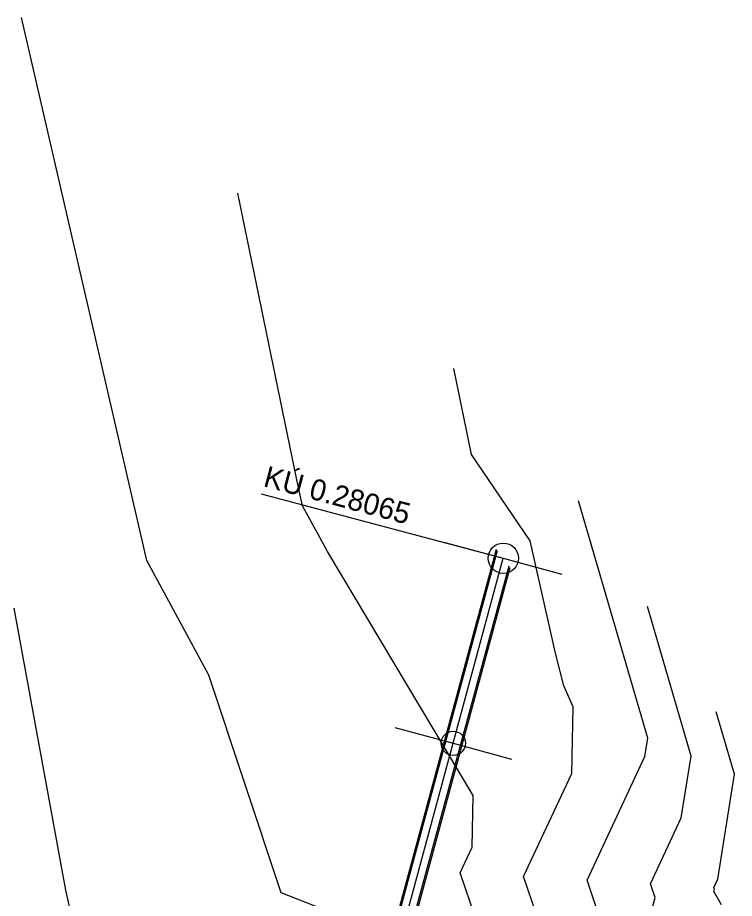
# Model space of a CAD drawing. Extents: x -549394 to -546608, y -1037055 to -1033629.
# Drawn here: x -547937.2 to -547818.7, y -1034382.6 to -1034237.1 of the extents above; entities that cross this region are included whole.
import ezdxf

# ---------------------------------------------------------------- set-up
doc = ezdxf.new("R2010")
doc.units = 0
for name, color, linetype in [('hlavni_vrst', 7, 'Continuous'), ('norm_vrst', 7, 'Continuous'), ('POLYGONY_SITUACE_PO', 7, 'Continuous'), ('u_sirka_0_5m', 7, 'Continuous'), ('x_navrh_C211', 7, 'Continuous'), ('x_osa_C211', 7, 'Continuous'), ('x_popis_oblouky_C211', 7, 'Continuous'), ('x_popis_pricne_rezy_C211', 7, 'Continuous')]:
    doc.layers.add(name, color=color, linetype=linetype)

msp = doc.modelspace()

# ---------------------------------------------------------------- linework, layer by layer
at = {"layer": 'hlavni_vrst'}
for p, q in [((-547862.16, -1034309.32), (-547865.08, -1034295.11)), ((-547852.46, -1034323.55), (-547862.16, -1034309.32)), ((-547848.25, -1034342.12), (-547852.46, -1034323.55)), ((-547846.88, -1034347.49), (-547848.25, -1034342.12)), ((-547845.37, -1034350.94), (-547846.88, -1034347.49)), ((-547845.58, -1034361.97), (-547845.37, -1034350.94)), ((-547853.56, -1034378.97), (-547845.58, -1034361.97)), ((-547851.42, -1034385.28), (-547853.56, -1034378.97))]:
    msp.add_line(p, q, dxfattribs=at)
at = {"layer": 'norm_vrst'}
for p, q in [((-547915.8, -1034326.78), (-547936.49, -1034237.14)), ((-547936.49, -1034237.14), (-547936.49, -1034237.14)), ((-547936.49, -1034237.14), (-547936.49, -1034237.14)), ((-547936.49, -1034237.14), (-547936.49, -1034237.14)), ((-547891.04, -1034313.49), (-547900.78, -1034266.13)), ((-547890.06, -1034317.76), (-547891.04, -1034313.49)), ((-547885.97, -1034325.32), (-547890.06, -1034317.76)), ((-547833.02, -1034356.15), (-547844.46, -1034316.94)), ((-547861.9, -1034365.62), (-547885.97, -1034325.32)), ((-547905.55, -1034345.73), (-547915.8, -1034326.78)), ((-547929.16, -1034381.23), (-547937.7, -1034334.69)), ((-547825.87, -1034359.12), (-547833.09, -1034334.37)), ((-547893.6, -1034381.7), (-547905.55, -1034345.73)), ((-547818.72, -1034362.08), (-547821.71, -1034351.8)), ((-547833.5, -1034359.17), (-547833.02, -1034356.15)), ((-547843.07, -1034379.57), (-547833.5, -1034359.17)), ((-547827.49, -1034369.31), (-547825.87, -1034359.12)), ((-547821.48, -1034379.45), (-547818.72, -1034362.08)), ((-547862.06, -1034374.14), (-547861.9, -1034365.62)), ((-547832.59, -1034380.18), (-547827.49, -1034369.31)), ((-547864.04, -1034378.36), (-547862.06, -1034374.14)), ((-547861.22, -1034386.68), (-547864.04, -1034378.36)), ((-547841.62, -1034383.88), (-547843.07, -1034379.57)), ((-547831.82, -1034382.47), (-547832.59, -1034380.18)), ((-547822.11, -1034380.79), (-547821.48, -1034379.45)), ((-547928.01, -1034386.66), (-547929.16, -1034381.23)), ((-547878.73, -1034387.48), (-547893.6, -1034381.7)), ((-547822.01, -1034381.07), (-547822.11, -1034380.79)), ((-547822.11, -1034381.45), (-547822.01, -1034381.07)), ((-547820.82, -1034383.64), (-547822.11, -1034381.45)), ((-547832.64, -1034385.6), (-547831.82, -1034382.47))]:
    msp.add_line(p, q, dxfattribs=at)
at = {"layer": 'POLYGONY_SITUACE_PO'}
msp.add_circle((-547856.9, -1034326.42), 2.5, dxfattribs=at)
at = {"layer": 'u_sirka_0_5m'}
msp.add_circle((-547865.17, -1034356.99), 2, dxfattribs=at)
at = {"layer": 'x_navrh_C211'}
for p, q in [((-547887.76, -1034435.68), (-547857.86, -1034325.17)), ((-547885.35, -1034436.34), (-547855.95, -1034327.68))]:
    msp.add_line(p, q, dxfattribs=at)
for points in [[(-547888, -1034435.62), (-547858.05, -1034324.91)], [(-547885.11, -1034436.4), (-547855.76, -1034327.93)]]:
    msp.add_lwpolyline(points, dxfattribs=at)
at = {"layer": 'x_osa_C211'}
msp.add_lwpolyline([(-547893.86, -1034463.03), (-547856.9, -1034326.42), (-547856.9, -1034326.42)], dxfattribs=at)
at = {"layer": 'x_popis_oblouky_C211'}
msp.add_lwpolyline([(-547896.89, -1034315.79), (-547856.9, -1034326.42)], dxfattribs=at)
at = {"layer": 'x_popis_pricne_rezy_C211'}
for points in [[(-547866.56, -1034323.81), (-547856.9, -1034326.42), (-547847.25, -1034329.04)], [(-547874.83, -1034354.37), (-547865.17, -1034356.99), (-547855.52, -1034359.6)]]:
    msp.add_lwpolyline(points, dxfattribs=at)

# ---------------------------------------------------------------- texts
at = {"layer": 'x_popis_oblouky_C211'}
msp.add_text('KÚ 0.28065', height=3.5, rotation=345.1109, dxfattribs=at).set_placement((-547896.72, -1034314.51))

doc.saveas('drawing.dxf')
